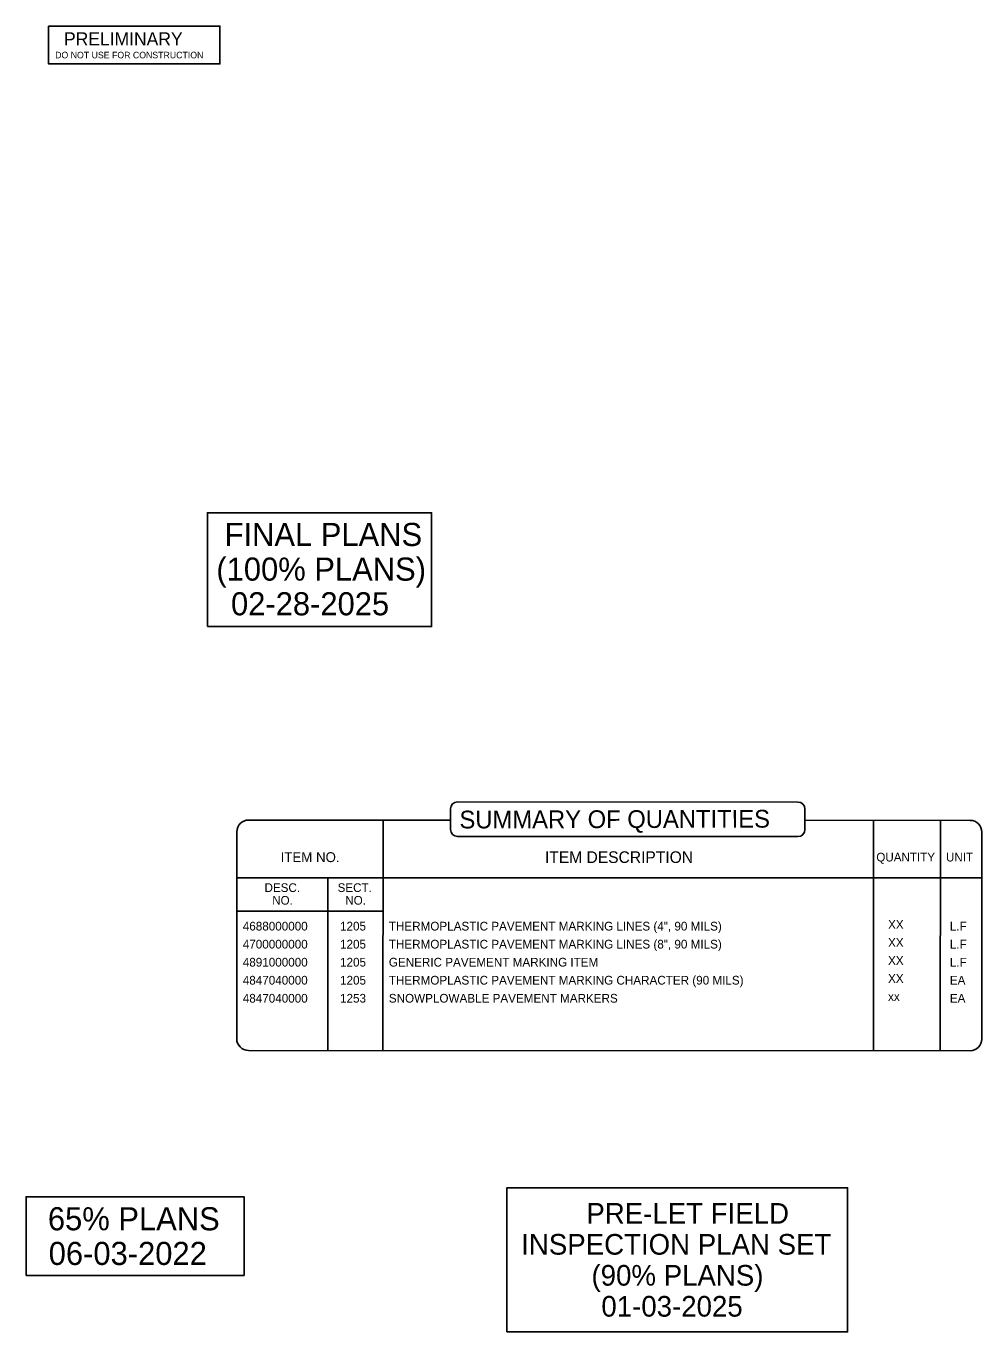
# Model space of a CAD drawing. Extents: x 2088685 to 2091711, y 751320 to 752417.
# Drawn here: x 2090981 to 2091711, y 751320 to 752319 of the extents above; entities that cross this region are included whole.
import ezdxf

# ---------------------------------------------------------------- set-up
doc = ezdxf.new("R2010")
doc.units = 0
for name, color, linetype in [('Default', 7, 'Continuous'), ('DEV PRELIMINARY STAMP CELL', 7, 'Continuous'), ('Gray Area Fill Shapes', 7, 'Continuous'), ('Sheet Sticker Incomplete CELL', 7, 'Continuous'), ('Sheet Title CELL', 7, 'Continuous')]:
    doc.layers.add(name, color=color, linetype=linetype)

msp = doc.modelspace()

# ---------------------------------------------------------------- linework, layer by layer
at = {"layer": 'Default'}
for p, q in [((2091253.38, 751535.64), (2091253.4, 751711.73)), ((2091628.31, 751535.5), (2091628.35, 751711.67)), ((2091679.16, 751535.48), (2091679.41, 751711.6)), ((2091141.67, 751667.73), (2091628.34, 751667.73)), ((2091211.11, 751535.66), (2091211.11, 751667.73)), ((2091628.34, 751667.73), (2091679.35, 751667.73)), ((2091679.35, 751667.73), (2091711.14, 751667.73)), ((2091141.65, 751642.15), (2091253.39, 751642.15)), ((2091211.59, 751643.27), (2091211.59, 751643.27)), ((2091211.59, 751629.49), (2091211.59, 751629.49))]:
    msp.add_line(p, q, dxfattribs=at)
at = {"layer": 'DEV PRELIMINARY STAMP CELL'}
msp.add_lwpolyline([(2090997.74, 752318.89), (2091128.75, 752318.89), (2091128.75, 752289.98), (2090997.74, 752289.98)], close=True, dxfattribs=at)
msp.add_lwpolyline([(2090997.74, 752318.89), (2091128.75, 752318.89), (2091128.75, 752289.98), (2090997.74, 752289.98)], close=True, dxfattribs=at)
at = {"layer": 'Gray Area Fill Shapes'}
msp.add_lwpolyline([(2090997.74, 752318.89), (2091128.75, 752318.89), (2091128.75, 752289.98), (2090997.74, 752289.98)], close=True, dxfattribs=at)
at = {"layer": 'Sheet Sticker Incomplete CELL'}
for points in [[(2091119.16, 751859.78), (2091119.16, 751946.8), (2091290.59, 751946.8), (2091290.59, 751859.78)], [(2091348.09, 751320.46), (2091348.09, 751430.66), (2091608.55, 751430.66), (2091608.55, 751320.46)], [(2090980.62, 751363.67), (2090980.62, 751423.73), (2091147.2, 751423.73), (2091147.2, 751363.67)]]:
    msp.add_lwpolyline(points, close=True, dxfattribs=at)
at = {"layer": 'Sheet Title CELL'}
for p, q in [((2091305.06, 751704.68), (2091305.07, 751720.39)), ((2091575.92, 751704.53), (2091575.92, 751720.24)), ((2091150.6, 751711.79), (2091305.06, 751711.71)), ((2091575.92, 751711.74), (2091702.25, 751711.58)), ((2091141.61, 751544.6), (2091141.68, 751702.88)), ((2091711.08, 751544.38), (2091711.15, 751702.66)), ((2091150.52, 751535.68), (2091702.16, 751535.47))]:
    msp.add_line(p, q, dxfattribs=at)
for points in [[(2091310.42, 751725.74), (2091570.58, 751725.59)], [(2091310.4, 751699.34), (2091570.57, 751699.18)]]:
    msp.add_lwpolyline(points, dxfattribs=at)
for centre, radius, start, end in [((2091310.41, 751720.39), 5.35, 89.97341, 179.97341), ((2091570.58, 751720.24), 5.35, 359.97341, 89.97341), ((2091150.59, 751702.88), 8.91, 89.97341, 179.97341), ((2091702.24, 751702.67), 8.91, 359.97341, 89.97341), ((2091310.41, 751704.68), 5.35, 179.97341, 269.97341), ((2091570.57, 751704.53), 5.35, 269.97341, 359.97341), ((2091150.52, 751544.59), 8.91, 179.97341, 269.97341), ((2091702.17, 751544.38), 8.91, 269.97341, 359.97341)]:
    msp.add_arc(centre, radius, start, end, dxfattribs=at)

# ---------------------------------------------------------------- texts
at = {"layer": 'Default'}
msp.add_text('SUMMARY OF QUANTITIES', height=13.5942, rotation=0.15565, dxfattribs=at).set_placement((2091311.86, 751705.39))
for s, height, p in [('ITEM NO.', 7.574, (2091175.19, 751679.67)), ('ITEM DESCRIPTION', 8.91, (2091377.19, 751679)), ('QUANTITY', 6.638, (2091630.48, 751680.14)), ('UNIT', 6.638, (2091683.73, 751680.14)), ('DESC.', 6.638, (2091162.85, 751656.83)), ('SECT.', 6.638, (2091218.71, 751656.83)), ('NO.', 6.638, (2091168.72, 751647.13)), ('NO.', 6.638, (2091224.58, 751647.13))]:
    msp.add_text(s, height=height, dxfattribs=at).set_placement(p)
at = {"layer": 'DEV PRELIMINARY STAMP CELL'}
for s, height, p in [(' PRELIMINARY', 9.9999, (2091005.87, 752304.13)), ('DO NOT USE FOR CONSTRUCTION', 5.0001, (2091002.81, 752294.26))]:
    msp.add_text(s, height=height, dxfattribs=at).set_placement(p)
at = {"layer": 'Sheet Sticker Incomplete CELL'}
for s, height, p in [('FINAL PLANS', 17.6708, (2091132.31, 751921.37)), ('(100% PLANS)', 17.6708, (2091126.03, 751894.87)), ('02-28-2025', 17.671, (2091137.23, 751868.36)), ('PRE-LET FIELD', 15.7916, (2091408.84, 751403.19)), ('65% PLANS', 17.671, (2090997.25, 751398.12)), ('06-03-2022', 17.671, (2090997.88, 751371.62)), ('INSPECTION PLAN SET', 15.7916, (2091359.05, 751379.51)), ('(90% PLANS)', 15.7916, (2091412.76, 751355.82)), ('01-03-2025', 15.792, (2091420.31, 751332.13))]:
    msp.add_text(s, height=height, rotation=360, dxfattribs=at).set_placement(p)
at = {"layer": 'Sheet Title CELL'}
for s, height, p in [('4688000000', 6.671, (2091146.23, 751627.36)), ('1205', 6.671, (2091220.56, 751627.36)), ('THERMOPLASTIC PAVEMENT MARKING LINES (4", 90 MILS)', 6.6709, (2091257.86, 751627.36)), ('XX', 6.671, (2091639.44, 751628.68)), ('L.F', 6.671, (2091686.66, 751627.36)), ('4700000000', 6.671, (2091146.23, 751613.58)), ('1205', 6.671, (2091220.56, 751613.58)), ('THERMOPLASTIC PAVEMENT MARKING LINES (8", 90 MILS)', 6.6709, (2091257.86, 751613.58)), ('XX', 6.671, (2091639.44, 751614.89)), ('L.F', 6.671, (2091686.66, 751613.58)), ('XX', 6.671, (2091639.44, 751601.11)), ('4891000000', 6.671, (2091146.23, 751599.79)), ('1205', 6.671, (2091220.56, 751599.79)), ('GENERIC PAVEMENT MARKING ITEM', 6.6709, (2091257.86, 751599.79)), ('L.F', 6.671, (2091686.66, 751599.79)), ('4847040000', 6.671, (2091146.23, 751586.01)), ('1205', 6.671, (2091220.56, 751586.01)), ('THERMOPLASTIC PAVEMENT MARKING CHARACTER (90 MILS)', 6.6709, (2091257.86, 751586.01)), ('XX', 6.671, (2091639.44, 751587.32)), ('EA', 6.671, (2091686.66, 751586.01)), ('4847040000', 6.671, (2091146.23, 751572.22)), ('1253', 6.671, (2091220.56, 751572.22)), ('SNOWPLOWABLE PAVEMENT MARKERS', 6.6709, (2091257.86, 751572.22)), ('xx', 6.671, (2091639.44, 751573.54)), ('EA', 6.671, (2091686.66, 751572.22))]:
    msp.add_text(s, height=height, dxfattribs=at).set_placement(p)

doc.saveas('drawing.dxf')
